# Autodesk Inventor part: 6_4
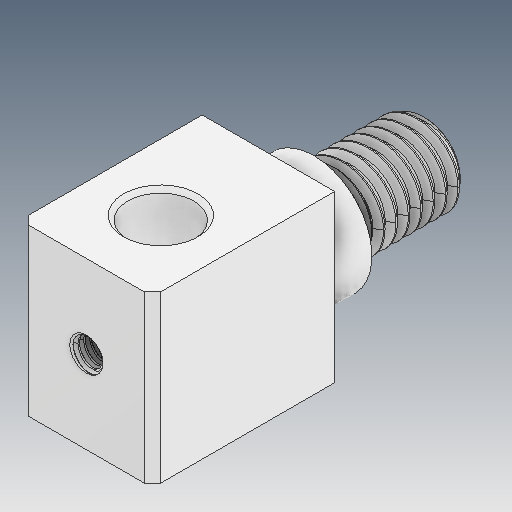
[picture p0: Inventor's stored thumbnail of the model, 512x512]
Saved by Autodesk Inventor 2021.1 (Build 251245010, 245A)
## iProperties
Created: 2021-06
Part Number: 6_4
Material: Ogólny
Document SubType Name: Modeling
Designer: user
Density: 1 g/cm^3
Appearance: Domyślna
Author: user
Revision Number: ÈÎºÎ
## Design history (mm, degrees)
feature "ÊäÈë1"
node "Bryła1"
